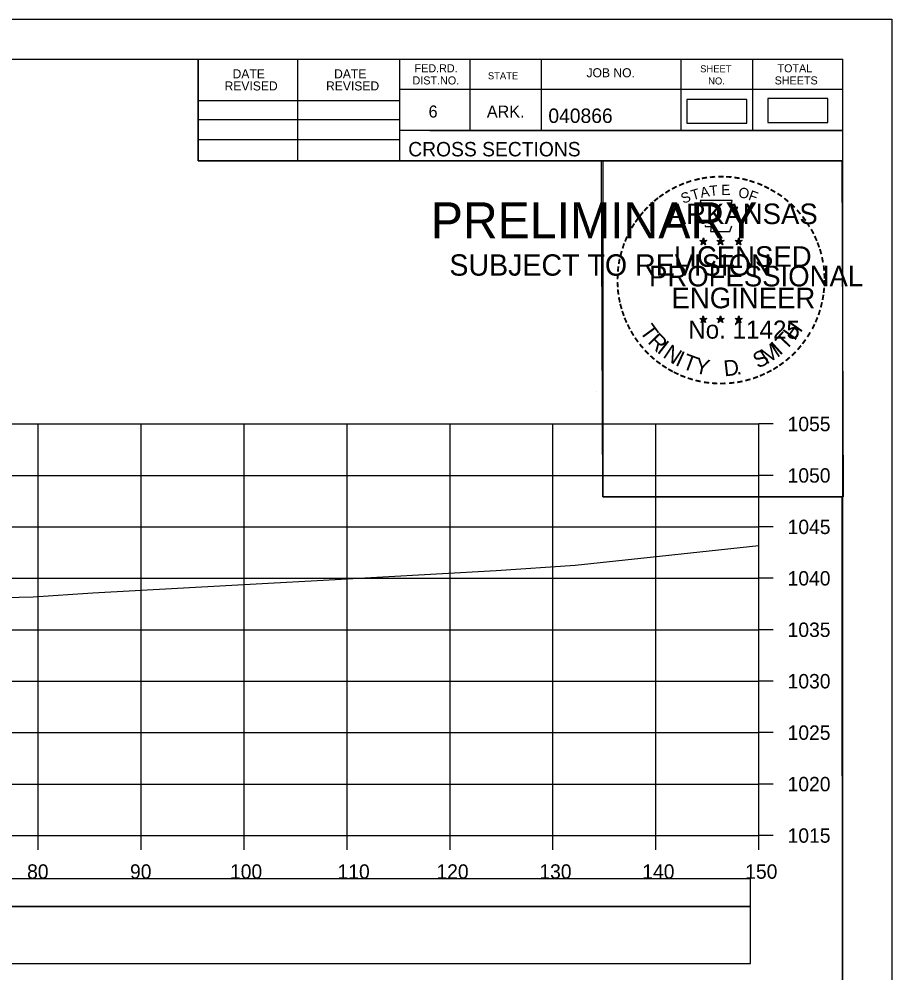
# Model space of a CAD drawing. Extents: x 1370565 to 1374448, y 301010 to 304637.
# Drawn here: x 1370813.2 to 1370898, y 303264.5 to 303357.2 of the extents above; entities that cross this region are included whole.
import ezdxf

# ---------------------------------------------------------------- set-up
doc = ezdxf.new("R2010")
doc.units = 0
for name, color, linetype in [('Default', 7, 'Continuous'), ('R_Axis', 7, 'Continuous'), ('R_Axis Annot', 7, 'Continuous'), ('R_Border', 7, 'Continuous'), ('R_Border PE', 7, 'Continuous'), ('R_Border Prem', 7, 'Continuous'), ('R_Drive', 7, 'Continuous'), ('R_Exist Surface', 7, 'Continuous'), ('R_Grid', 7, 'Continuous'), ('R_No Plot', 7, 'Continuous')]:
    doc.layers.add(name, color=color, linetype=linetype)

msp = doc.modelspace()

# ---------------------------------------------------------------- linework, layer by layer
at = {"layer": 'Default'}
msp.add_lwpolyline([(1370878.019, 303347.097), (1370883.853, 303347.097), (1370883.853, 303349.407), (1370878.019, 303349.407)], close=True, dxfattribs=at)
at = {"layer": 'R_Axis'}
for p, q in [((1370885.026, 303277.856), (1370885.026, 303317.856)), ((1370886.426, 303317.856), (1370885.026, 303317.856)), ((1370886.426, 303312.856), (1370885.026, 303312.856)), ((1370886.426, 303307.856), (1370885.026, 303307.856)), ((1370886.426, 303302.856), (1370885.026, 303302.856)), ((1370886.426, 303297.856), (1370885.026, 303297.856)), ((1370886.426, 303292.856), (1370885.026, 303292.856)), ((1370886.426, 303287.856), (1370885.026, 303287.856)), ((1370886.426, 303282.856), (1370885.026, 303282.856)), ((1370585.026, 303277.856), (1370885.026, 303277.856)), ((1370815.026, 303276.456), (1370815.026, 303277.856)), ((1370825.026, 303276.456), (1370825.026, 303277.856)), ((1370835.026, 303276.456), (1370835.026, 303277.856)), ((1370845.026, 303276.456), (1370845.026, 303277.856)), ((1370855.026, 303276.456), (1370855.026, 303277.856)), ((1370865.026, 303276.456), (1370865.026, 303277.856)), ((1370875.026, 303276.456), (1370875.026, 303277.856)), ((1370885.026, 303276.456), (1370885.026, 303277.856)), ((1370886.426, 303277.856), (1370885.026, 303277.856))]:
    msp.add_line(p, q, dxfattribs=at)
at = {"layer": 'R_Border'}
for p, q in [((1370577.026, 303353.316), (1370893.206, 303353.316)), ((1370830.566, 303343.436), (1370830.566, 303353.316)), ((1370840.246, 303343.436), (1370840.246, 303353.316)), ((1370850.106, 303353.316), (1370850.106, 303343.436)), ((1370856.946, 303353.316), (1370856.946, 303346.376)), ((1370863.886, 303353.316), (1370863.886, 303346.376)), ((1370877.466, 303353.316), (1370877.466, 303346.376)), ((1370884.406, 303353.316), (1370884.406, 303346.376)), ((1370893.206, 303147.856), (1370893.206, 303353.316)), ((1370893.206, 303350.376), (1370850.106, 303350.376)), ((1370893.206, 303350.396), (1370893.206, 303350.396)), ((1370830.566, 303349.296), (1370850.106, 303349.296)), ((1370830.566, 303347.436), (1370850.106, 303347.436)), ((1370893.206, 303346.376), (1370850.106, 303346.376)), ((1370853.066, 303346.376), (1370893.206, 303346.376)), ((1370830.566, 303345.496), (1370850.106, 303345.496)), ((1370893.206, 303343.436), (1370830.566, 303343.436))]:
    msp.add_line(p, q, dxfattribs=at)
at = {"layer": 'R_Border PE'}
for p, q in [((1370879.64, 303335.945), (1370879.599, 303335.693)), ((1370879.64, 303335.58), (1370879.64, 303335.945)), ((1370879.64, 303335.945), (1370879.689, 303335.695)), ((1370881.31, 303335.945), (1370881.269, 303335.693)), ((1370881.31, 303335.58), (1370881.31, 303335.945)), ((1370881.31, 303335.945), (1370881.359, 303335.695)), ((1370883.074, 303335.933), (1370883.033, 303335.681)), ((1370883.074, 303335.568), (1370883.074, 303335.933)), ((1370883.074, 303335.933), (1370883.123, 303335.683)), ((1370879.291, 303335.691), (1370879.64, 303335.58)), ((1370879.291, 303335.691), (1370879.544, 303335.646)), ((1370879.291, 303335.691), (1370879.528, 303335.569)), ((1370879.424, 303335.283), (1370879.64, 303335.58)), ((1370879.424, 303335.283), (1370879.55, 303335.527)), ((1370879.424, 303335.283), (1370879.638, 303335.5)), ((1370879.853, 303335.283), (1370879.638, 303335.497)), ((1370879.987, 303335.691), (1370879.64, 303335.58)), ((1370879.853, 303335.283), (1370879.64, 303335.58)), ((1370879.987, 303335.691), (1370879.701, 303335.642)), ((1370879.853, 303335.283), (1370879.716, 303335.574)), ((1370879.987, 303335.691), (1370879.783, 303335.589)), ((1370880.961, 303335.691), (1370881.31, 303335.58)), ((1370880.961, 303335.691), (1370881.214, 303335.646)), ((1370880.961, 303335.691), (1370881.198, 303335.569)), ((1370881.094, 303335.283), (1370881.31, 303335.58)), ((1370881.094, 303335.283), (1370881.22, 303335.527)), ((1370881.094, 303335.283), (1370881.308, 303335.5)), ((1370881.523, 303335.283), (1370881.308, 303335.497)), ((1370881.657, 303335.691), (1370881.31, 303335.58)), ((1370881.523, 303335.283), (1370881.31, 303335.58)), ((1370881.657, 303335.691), (1370881.371, 303335.642)), ((1370881.523, 303335.283), (1370881.386, 303335.574)), ((1370881.657, 303335.691), (1370881.453, 303335.589)), ((1370882.725, 303335.679), (1370883.074, 303335.568)), ((1370882.725, 303335.679), (1370882.978, 303335.634)), ((1370882.725, 303335.679), (1370882.962, 303335.557)), ((1370882.858, 303335.271), (1370883.074, 303335.568)), ((1370882.858, 303335.271), (1370882.984, 303335.515)), ((1370882.858, 303335.271), (1370883.072, 303335.488)), ((1370883.287, 303335.271), (1370883.072, 303335.485)), ((1370883.421, 303335.679), (1370883.074, 303335.568)), ((1370883.287, 303335.271), (1370883.074, 303335.568)), ((1370883.421, 303335.679), (1370883.135, 303335.63)), ((1370883.287, 303335.271), (1370883.15, 303335.562)), ((1370883.421, 303335.679), (1370883.217, 303335.577)), ((1370879.636, 303328.372), (1370879.595, 303328.12)), ((1370879.636, 303328.007), (1370879.636, 303328.372)), ((1370879.636, 303328.372), (1370879.685, 303328.122)), ((1370881.305, 303328.372), (1370881.264, 303328.12)), ((1370881.305, 303328.007), (1370881.305, 303328.372)), ((1370881.305, 303328.372), (1370881.354, 303328.122)), ((1370883.072, 303328.362), (1370883.031, 303328.11)), ((1370883.072, 303327.997), (1370883.072, 303328.362)), ((1370883.072, 303328.362), (1370883.121, 303328.112)), ((1370879.287, 303328.118), (1370879.636, 303328.007)), ((1370879.287, 303328.118), (1370879.54, 303328.073)), ((1370879.287, 303328.118), (1370879.524, 303327.996)), ((1370879.42, 303327.71), (1370879.636, 303328.007)), ((1370879.42, 303327.71), (1370879.546, 303327.954)), ((1370879.42, 303327.71), (1370879.634, 303327.927)), ((1370879.849, 303327.71), (1370879.634, 303327.924)), ((1370879.983, 303328.118), (1370879.636, 303328.007)), ((1370879.849, 303327.71), (1370879.636, 303328.007)), ((1370879.983, 303328.118), (1370879.697, 303328.069)), ((1370879.849, 303327.71), (1370879.712, 303328.001)), ((1370879.983, 303328.118), (1370879.779, 303328.016)), ((1370880.956, 303328.118), (1370881.305, 303328.007)), ((1370880.956, 303328.118), (1370881.209, 303328.073)), ((1370880.956, 303328.118), (1370881.193, 303327.996)), ((1370881.089, 303327.71), (1370881.305, 303328.007)), ((1370881.089, 303327.71), (1370881.215, 303327.954)), ((1370881.089, 303327.71), (1370881.303, 303327.927)), ((1370881.518, 303327.71), (1370881.303, 303327.924)), ((1370881.652, 303328.118), (1370881.305, 303328.007)), ((1370881.518, 303327.71), (1370881.305, 303328.007)), ((1370881.652, 303328.118), (1370881.366, 303328.069)), ((1370881.518, 303327.71), (1370881.381, 303328.001)), ((1370881.652, 303328.118), (1370881.448, 303328.016)), ((1370882.723, 303328.108), (1370883.072, 303327.997)), ((1370882.723, 303328.108), (1370882.976, 303328.063)), ((1370882.723, 303328.108), (1370882.96, 303327.986)), ((1370882.856, 303327.7), (1370883.072, 303327.997)), ((1370882.856, 303327.7), (1370882.982, 303327.944)), ((1370882.856, 303327.7), (1370883.07, 303327.917)), ((1370883.285, 303327.7), (1370883.07, 303327.914)), ((1370883.419, 303328.108), (1370883.072, 303327.997)), ((1370883.285, 303327.7), (1370883.072, 303327.997)), ((1370883.419, 303328.108), (1370883.133, 303328.059)), ((1370883.285, 303327.7), (1370883.148, 303327.991)), ((1370883.419, 303328.108), (1370883.215, 303328.006))]:
    msp.add_line(p, q, dxfattribs=at)
for points in [[(1370879.332, 303339.569), (1370879.601, 303338.742)], [(1370882.843, 303338.647), (1370882.985, 303338.931), (1370882.3, 303338.907), (1370882.448, 303339.569), (1370879.332, 303339.569)], [(1370879.824, 303337.146), (1370879.824, 303337.059), (1370880.387, 303337.04), (1370880.333, 303336.567), (1370882.203, 303336.567), (1370882.404, 303337.103)], [(1370879.64, 303335.945), (1370879.853, 303335.283), (1370879.291, 303335.691), (1370879.987, 303335.691), (1370879.424, 303335.283), (1370879.64, 303335.945)], [(1370881.31, 303335.945), (1370881.523, 303335.283), (1370880.961, 303335.691), (1370881.657, 303335.691), (1370881.094, 303335.283), (1370881.31, 303335.945)], [(1370883.074, 303335.933), (1370883.287, 303335.271), (1370882.725, 303335.679), (1370883.421, 303335.679), (1370882.858, 303335.271), (1370883.074, 303335.933)], [(1370879.636, 303328.372), (1370879.849, 303327.71), (1370879.287, 303328.118), (1370879.983, 303328.118), (1370879.42, 303327.71), (1370879.636, 303328.372)], [(1370881.305, 303328.372), (1370881.518, 303327.71), (1370880.956, 303328.118), (1370881.652, 303328.118), (1370881.089, 303327.71), (1370881.305, 303328.372)], [(1370883.072, 303328.362), (1370883.285, 303327.7), (1370882.723, 303328.108), (1370883.419, 303328.108), (1370882.856, 303327.7), (1370883.072, 303328.362)]]:
    msp.add_lwpolyline(points, dxfattribs=at)
for centre, radius in [((1370879.639, 303335.579), 0.172), ((1370879.639, 303335.579), 0.145), ((1370881.309, 303335.579), 0.172), ((1370881.309, 303335.579), 0.145), ((1370883.073, 303335.567), 0.172), ((1370879.639, 303335.579), 0.116), ((1370879.639, 303335.579), 0.0991), ((1370879.639, 303335.579), 0.0747), ((1370879.639, 303335.579), 0.0495), ((1370879.639, 303335.579), 0.0296), ((1370881.309, 303335.579), 0.116), ((1370881.309, 303335.579), 0.0991), ((1370881.309, 303335.579), 0.0747), ((1370881.309, 303335.579), 0.0495), ((1370881.309, 303335.579), 0.0296), ((1370883.073, 303335.567), 0.145), ((1370883.073, 303335.567), 0.116), ((1370883.073, 303335.567), 0.0991), ((1370883.073, 303335.567), 0.0747), ((1370883.073, 303335.567), 0.0495), ((1370883.073, 303335.567), 0.0296), ((1370879.635, 303328.006), 0.172), ((1370879.635, 303328.006), 0.145), ((1370879.635, 303328.006), 0.116), ((1370879.635, 303328.006), 0.0991), ((1370879.635, 303328.006), 0.0747), ((1370879.635, 303328.006), 0.0495), ((1370879.635, 303328.006), 0.0296), ((1370881.304, 303328.006), 0.172), ((1370881.304, 303328.006), 0.145), ((1370881.304, 303328.006), 0.116), ((1370881.304, 303328.006), 0.0991), ((1370881.304, 303328.006), 0.0747), ((1370881.304, 303328.006), 0.0495), ((1370881.304, 303328.006), 0.0296), ((1370883.071, 303327.996), 0.172), ((1370883.071, 303327.996), 0.145), ((1370883.071, 303327.996), 0.116), ((1370883.071, 303327.996), 0.0991), ((1370883.071, 303327.996), 0.0747), ((1370883.071, 303327.996), 0.0495), ((1370883.071, 303327.996), 0.0296)]:
    msp.add_circle(centre, radius, dxfattribs=at)
at = {"layer": 'R_Drive'}
for points in [[(1370885.889, 303347.168), (1370891.723, 303347.168), (1370891.723, 303349.478), (1370885.889, 303349.478)], [(1370585.817, 303270.95), (1370884.235, 303270.95), (1370884.235, 303273.656), (1370585.817, 303273.656)], [(1370585.817, 303265.428), (1370884.235, 303265.428), (1370884.235, 303270.95), (1370585.817, 303270.95)]]:
    msp.add_lwpolyline(points, close=True, dxfattribs=at)
at = {"layer": 'R_Exist Surface'}
msp.add_lwpolyline([(1370661.698, 303296.637), (1370680.076, 303297.787), (1370714.105, 303299.446), (1370714.711, 303299.475), (1370714.906, 303299.426), (1370731.823, 303295.634), (1370732.35, 303295.717), (1370747.503, 303298.292), (1370753.267, 303298.823), (1370758.728, 303299.298), (1370768.149, 303299.982), (1370768.831, 303300.033), (1370769.701, 303300.025), (1370790.867, 303300.137), (1370798.816, 303300.394), (1370806.32, 303300.863), (1370814.546, 303301.055), (1370820.33, 303301.431), (1370837.361, 303302.381), (1370842.129, 303302.635), (1370859.517, 303303.604), (1370867.187, 303304.14), (1370873.55, 303304.804), (1370885.026, 303306.048)], dxfattribs=at)
at = {"layer": 'R_Grid'}
for p, q in [((1370585.026, 303317.856), (1370885.026, 303317.856)), ((1370815.026, 303277.856), (1370815.026, 303317.856)), ((1370825.026, 303277.856), (1370825.026, 303317.856)), ((1370835.026, 303277.856), (1370835.026, 303317.856)), ((1370845.026, 303277.856), (1370845.026, 303317.856)), ((1370855.026, 303277.856), (1370855.026, 303317.856)), ((1370865.026, 303277.856), (1370865.026, 303317.856)), ((1370875.026, 303277.856), (1370875.026, 303317.856)), ((1370885.026, 303277.856), (1370885.026, 303317.856)), ((1370585.026, 303312.856), (1370885.026, 303312.856)), ((1370585.026, 303307.856), (1370885.026, 303307.856)), ((1370585.026, 303302.856), (1370885.026, 303302.856)), ((1370585.026, 303297.856), (1370885.026, 303297.856)), ((1370585.026, 303292.856), (1370885.026, 303292.856)), ((1370585.026, 303287.856), (1370885.026, 303287.856)), ((1370585.026, 303282.856), (1370885.026, 303282.856)), ((1370585.026, 303277.856), (1370885.026, 303277.856))]:
    msp.add_line(p, q, dxfattribs=at)
at = {"layer": 'R_No Plot'}
for p, q in [((1370564.625, 303357.21), (1370897.958, 303357.21)), ((1370869.24, 303320.98), (1370869.24, 303320.98))]:
    msp.add_line(p, q, dxfattribs=at)
for points in [[(1370564.618, 303357.21), (1370897.958, 303357.21), (1370897.958, 303143.873), (1370564.618, 303143.873)], [(1370810.946, 303353.316), (1370830.566, 303353.316), (1370830.566, 303343.436), (1370846.678, 303343.436), (1370869.877, 303343.436), (1370869.877, 303310.765), (1370893.085, 303310.765), (1370893.206, 303147.856), (1370577.026, 303147.856), (1370577.026, 303353.316)], [(1370869.737, 303343.436), (1370893.085, 303343.436), (1370893.225, 303310.765), (1370869.877, 303310.765)]]:
    msp.add_lwpolyline(points, close=True, dxfattribs=at)

# ---------------------------------------------------------------- texts
at = {"layer": 'R_Axis Annot'}
for s, p in [('1055', (1370887.826, 303317.156)), ('1050', (1370887.826, 303312.156)), ('1045', (1370887.826, 303307.156)), ('1040', (1370887.826, 303302.156)), ('1035', (1370887.826, 303297.156)), ('1030', (1370887.826, 303292.156)), ('1025', (1370887.826, 303287.156)), ('1020', (1370887.826, 303282.156)), ('1015', (1370887.826, 303277.156)), ('80', (1370813.94, 303273.656)), ('90', (1370823.94, 303273.656)), ('100', (1370833.653, 303273.656)), ('110', (1370844.105, 303273.656)), ('120', (1370853.709, 303273.656)), ('130', (1370863.709, 303273.656)), ('140', (1370873.709, 303273.656)), ('150', (1370883.709, 303273.656))]:
    msp.add_text(s, height=1.4, dxfattribs=at).set_placement(p)
at = {"layer": 'R_Border'}
for s, height, p in [('FED.RD.', 0.7819, (1370851.586, 303352.036)), ('JOB NO.', 0.8792, (1370868.286, 303351.556)), ('SHEET', 0.684, (1370879.326, 303352.036)), ('TOTAL', 0.7819, (1370886.846, 303352.036)), ('DATE', 0.8792, (1370833.904, 303351.452)), ('DATE', 0.8792, (1370843.764, 303351.452)), ('DIST.NO.', 0.7819, (1370851.386, 303350.856)), ('STATE', 0.684, (1370858.706, 303351.356)), ('NO.', 0.684, (1370880.106, 303350.856)), ('SHEETS', 0.7819, (1370886.566, 303350.856)), ('REVISED', 0.8792, (1370833.124, 303350.272)), ('REVISED', 0.8792, (1370842.984, 303350.272)), ('6', 1.172, (1370852.946, 303347.636)), ('ARK.', 1.1723, (1370858.606, 303347.636)), ('040866', 1.4, (1370864.582, 303347.115)), ('CROSS SECTIONS', 1.4, (1370850.969, 303343.866))]:
    msp.add_text(s, height=height, rotation=360, dxfattribs=at).set_placement(p)
at = {"layer": 'R_Border PE'}
for s, height, rotation, p in [('-', 1.6, 24.30721, (1370877.446, 303340.427)), ('-', 1.6, 19.17608, (1370878.08, 303340.696)), ('-', 1.6, 13.63015, (1370878.83, 303340.937)), ('-', 1.6, 10.21935, (1370879.508, 303341.099)), ('-', 1.6, 5.89682, (1370880.237, 303341.209)), ('-', 1.6, 0.18623, (1370881.009, 303341.281)), ('-', 1.6, 357.74304, (1370881.732, 303341.268)), ('-', 1.6, 352.16172, (1370882.476, 303341.212)), ('-', 1.6, 347.20489, (1370883.195, 303341.098)), ('-', 1.6, 342.3362, (1370883.83, 303340.943)), ('-', 1.6, 337.85509, (1370884.565, 303340.72)), ('-', 1.6, 34.06357, (1370876.216, 303339.74)), ('-', 1.6, 28.79182, (1370876.813, 303340.11)), ('S', 1, 21.59401, (1370877.687, 303339.247)), ('T', 1, 16.4036, (1370878.601, 303339.578)), ('A', 1, 11.21318, (1370879.427, 303339.829)), ('T', 1, 6.02276, (1370880.276, 303339.995)), ('E', 1, 0.83234, (1370881.381, 303340.105)), ('O', 1, 350.4515, (1370882.985, 303339.895)), ('F', 1, 340.07066, (1370883.939, 303339.667)), ('-', 1.6, 334.12109, (1370885.196, 303340.449)), ('-', 1.6, 329.64089, (1370885.775, 303340.166)), ('-', 1.6, 42.96224, (1370874.729, 303338.55)), ('-', 1.6, 38.95066, (1370875.162, 303338.967)), ('-', 1.6, 36.23174, (1370875.638, 303339.345)), ('-', 1.6, 325.86266, (1370886.418, 303339.805)), ('-', 1.6, 320.52971, (1370887.028, 303339.379)), ('-', 1.6, 50.61417, (1370873.878, 303337.586)), ('-', 1.6, 48.42305, (1370874.281, 303338.072)), ('ARKANSAS', 2, 360, (1370876.185, 303337.281)), ('-', 1.6, 315.57859, (1370887.627, 303338.891)), ('-', 1.6, 309.87973, (1370888.196, 303338.341)), ('-', 1.6, 54.23247, (1370873.465, 303337.019)), ('-', 1.6, 306.65218, (1370888.721, 303337.739)), ('-', 1.6, 62.87135, (1370872.827, 303335.878)), ('-', 1.6, 58.07063, (1370873.14, 303336.492)), ('-', 1.4, 303.67529, (1370889.207, 303337.171)), ('-', 1.6, 299.66835, (1370889.526, 303336.564)), ('-', 1.6, 67.77427, (1370872.568, 303335.267)), ('-', 1.6, 294.66279, (1370889.85, 303335.952)), ('-', 1.6, 72.39447, (1370872.349, 303334.637)), ('LICENSED', 2, 360, (1370876.782, 303333.132)), ('DWB', 0.01, 360, (1370879.627, 303335.575)), ('DWB', 0.01, 360, (1370881.297, 303335.575)), ('DWB', 0.01, 360, (1370883.061, 303335.564)), ('-', 1.6, 290.57283, (1370890.107, 303335.375)), ('-', 1.6, 285.12326, (1370890.341, 303334.795)), ('-', 1.6, 81.20126, (1370872.02, 303333.21)), ('-', 1.6, 75.46096, (1370872.152, 303333.923)), ('-', 1.6, 280.54934, (1370890.541, 303334.053)), ('-', 1.6, 85.18634, (1370871.944, 303332.519)), ('PROFESSIONAL', 2, 360, (1370874.359, 303331.228)), ('-', 1.6, 276.59616, (1370890.703, 303333.285)), ('-', 1.6, 89.06224, (1370871.919, 303331.818)), ('-', 1.6, 274.33011, (1370890.763, 303332.563)), ('-', 1.6, 94.19588, (1370871.954, 303331.093)), ('ENGINEER', 2, 360, (1370876.546, 303329.103)), ('-', 1.6, 263.5172, (1370890.778, 303331.265)), ('-', 1.6, 269.94067, (1370890.797, 303331.931)), ('-', 1.6, 98.94793, (1370872.026, 303330.426)), ('-', 1.6, 101.71495, (1370872.161, 303329.693)), ('-', 1.6, 260.99529, (1370890.707, 303330.611)), ('-', 1.6, 105.45785, (1370872.323, 303329.098)), ('-', 1.6, 255.7626, (1370890.597, 303329.933)), ('-', 1.6, 109.08742, (1370872.538, 303328.467)), ('-', 1.6, 252.86809, (1370890.416, 303329.213)), ('-', 1.6, 114.06432, (1370872.792, 303327.871)), ('-', 1.6, 115.72885, (1370873.097, 303327.253)), ('T', 1.54, 306.04056, (1370873.395, 303326.845)), ('No. 11425', 1.757, 360, (1370878.173, 303326.152)), ('DWB', 0.01, 360, (1370879.623, 303328.002)), ('DWB', 0.01, 360, (1370881.292, 303328.002)), ('DWB', 0.01, 360, (1370883.059, 303327.992)), ('H', 1.54, 54.60883, (1370888.516, 303325.88)), ('-', 1.6, 244.61971, (1370889.931, 303327.911)), ('-', 1.6, 247.88866, (1370890.193, 303328.54)), ('-', 1.6, 120.44712, (1370873.454, 303326.667)), ('R', 1.54, 314.00497, (1370874.158, 303325.797)), ('T', 1.54, 46.64442, (1370887.626, 303324.938)), ('-', 1.6, 239.07125, (1370889.537, 303327.159)), ('-', 1.6, 125.89344, (1370873.857, 303326.106)), ('-', 1.6, 130.71812, (1370874.319, 303325.554)), ('I', 1.54, 321.96938, (1370875.058, 303324.865)), ('N', 1.54, 326.50021, (1370875.625, 303324.394)), ('M', 1.54, 32.65632, (1370885.78, 303323.613)), ('I', 1.54, 42.11359, (1370887.064, 303324.46)), ('-', 1.6, 231.25377, (1370888.705, 303325.94)), ('-', 1.6, 233.84524, (1370889.135, 303326.506)), ('-', 1.6, 134.22381, (1370874.836, 303325.009)), ('I', 1.54, 335.36034, (1370876.834, 303323.608)), ('T', 1.54, 339.89117, (1370877.495, 303323.28)), ('S', 1.54, 26.9312, (1370884.941, 303323.207)), ('-', 1.6, 225.76533, (1370888.226, 303325.376)), ('-', 1.6, 138.93382, (1370875.361, 303324.545)), ('-', 1.6, 144.64634, (1370875.917, 303324.139)), ('Y', 1.54, 347.85558, (1370878.712, 303322.835)), ('D', 1.54, 6.39691, (1370881.696, 303322.476)), ('-', 1.6, 215.73633, (1370887.155, 303324.395)), ('-', 1.6, 221.08509, (1370887.704, 303324.867)), ('-', 1.6, 148.08978, (1370876.478, 303323.768)), ('-', 1.6, 151.57039, (1370877.057, 303323.443)), ('-', 1.6, 154.60019, (1370877.579, 303323.196)), ('.', 1.54, 13.76417, (1370882.889, 303322.604)), ('-', 1.6, 204.25161, (1370885.439, 303323.343)), ('-', 1.6, 207.35684, (1370886.063, 303323.662)), ('-', 1.6, 212.24909, (1370886.621, 303324.008)), ('-', 1.6, 158.56121, (1370878.203, 303322.942)), ('-', 1.6, 162.79826, (1370878.89, 303322.729)), ('-', 1.6, 167.55551, (1370879.605, 303322.565)), ('-', 1.6, 173.11546, (1370880.377, 303322.455)), ('-', 1.6, 176.51827, (1370881.125, 303322.402)), ('-', 1.6, 181.59176, (1370881.869, 303322.421)), ('-', 1.6, 185.81666, (1370882.678, 303322.497)), ('-', 1.6, 191.28576, (1370883.414, 303322.629)), ('-', 1.6, 195.47429, (1370884.143, 303322.828)), ('-', 1.6, 200.71842, (1370884.82, 303323.07))]:
    msp.add_text(s, height=height, rotation=rotation, dxfattribs=at).set_placement(p)
at = {"layer": 'R_Border Prem'}
for s, height, p in [('PRELIMINARY', 3.5, (1370853.157, 303335.899)), ('DWB', 0.01, (1370853.904, 303337.748)), ('SUBJECT TO REVISION', 2.07511, (1370854.966, 303332.27))]:
    msp.add_text(s, height=height, rotation=360, dxfattribs=at).set_placement(p)

doc.saveas('drawing.dxf')
